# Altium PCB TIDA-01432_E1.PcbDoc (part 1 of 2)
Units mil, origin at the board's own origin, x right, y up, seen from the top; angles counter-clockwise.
Board outline 1228.35 x 2074.8 mil, 4 copper layers (Top Layer, Signal Layer 1, Signal Layer 2, Bottom Layer), stack 61.6 mil thick; 90 components, 49 nets, 292 pads, 293 vias.
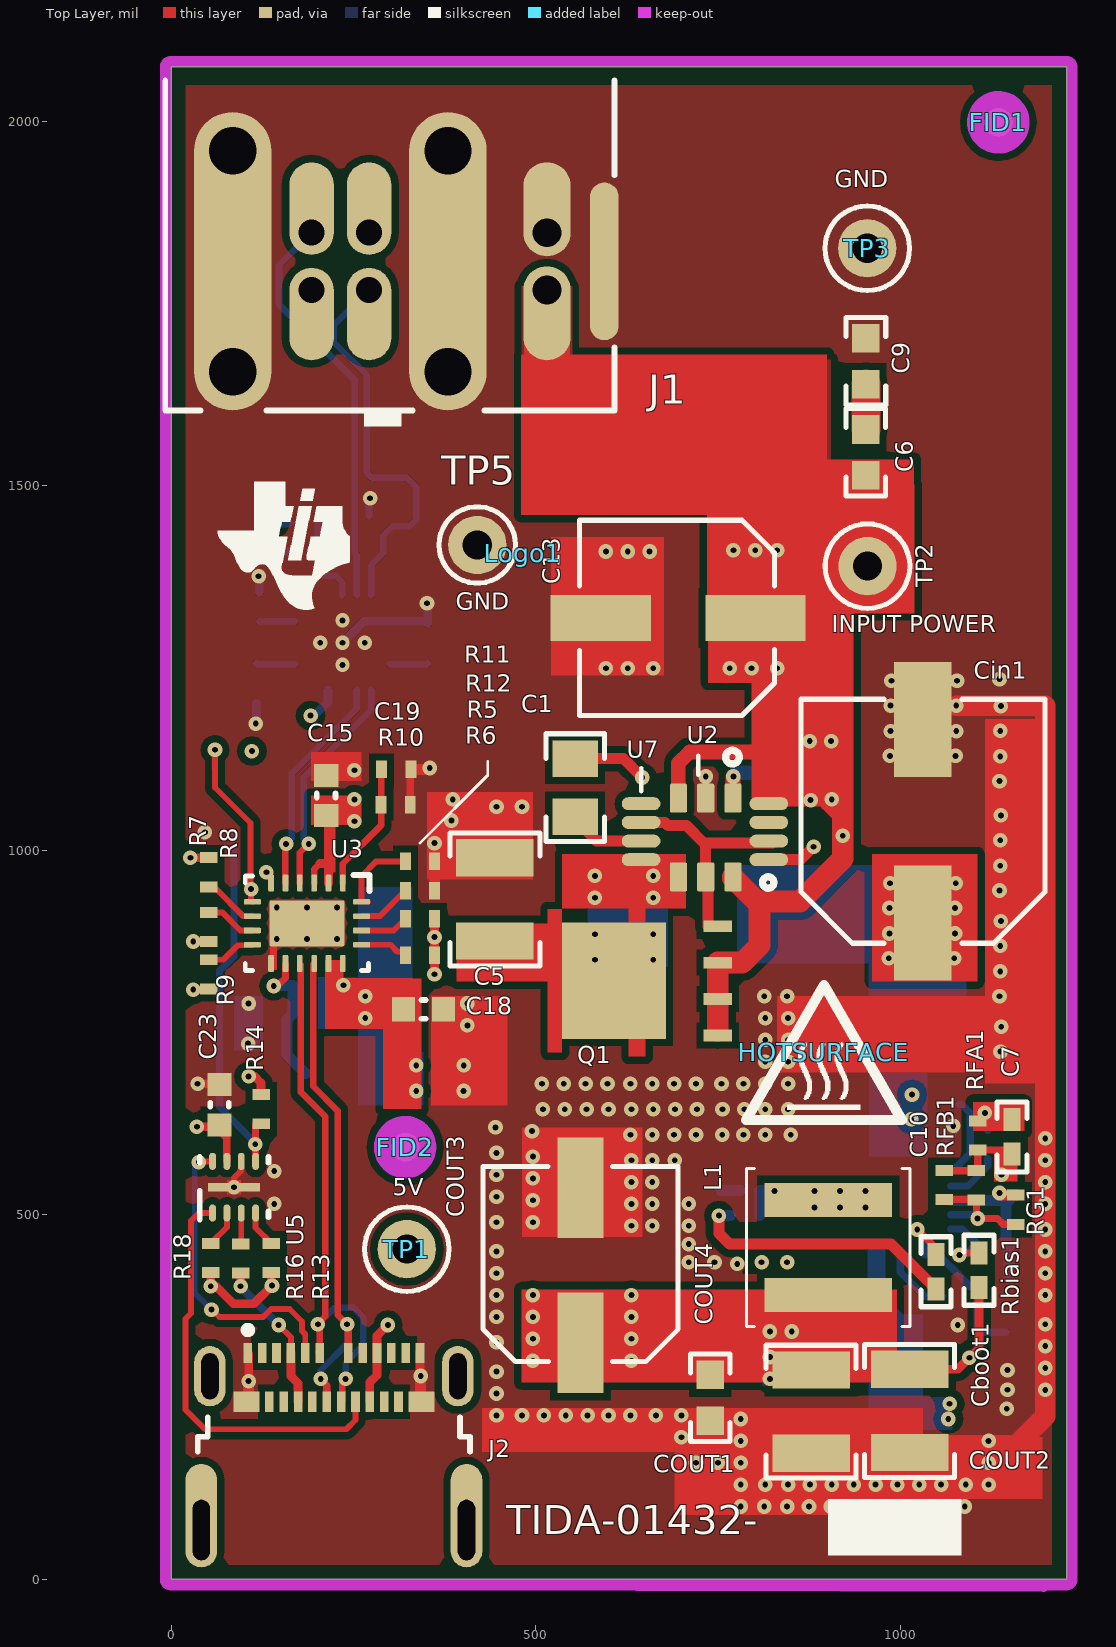
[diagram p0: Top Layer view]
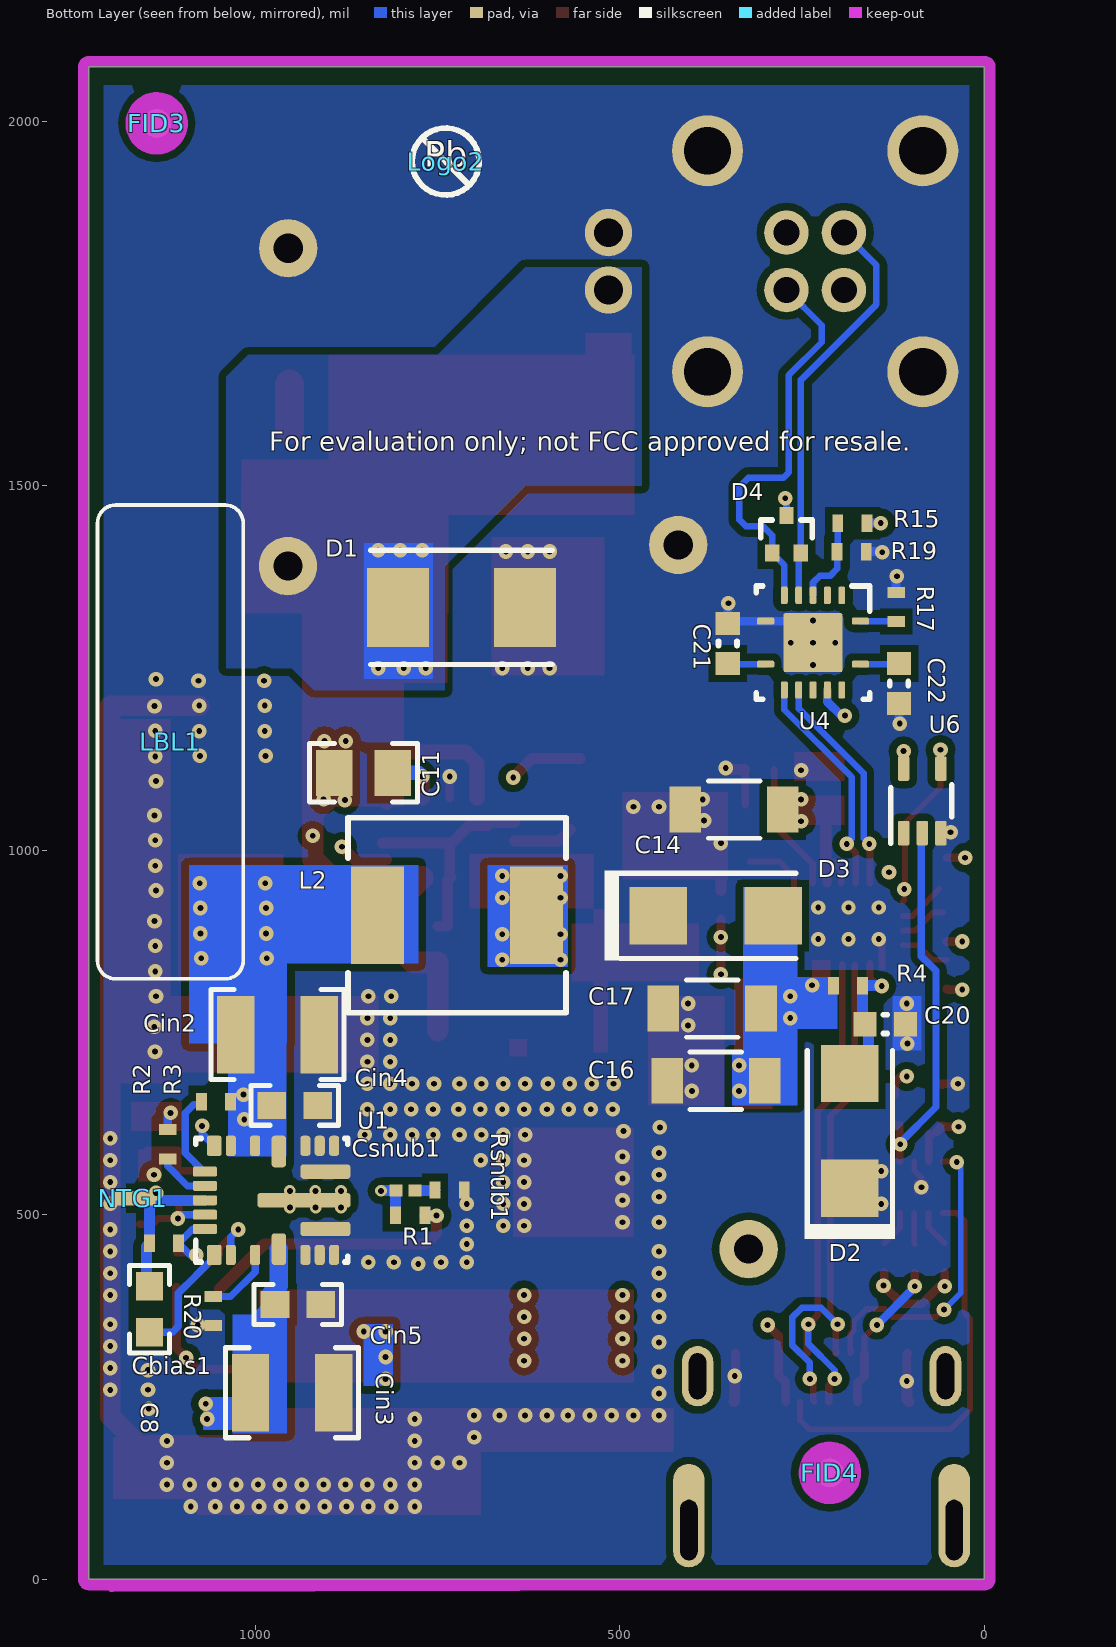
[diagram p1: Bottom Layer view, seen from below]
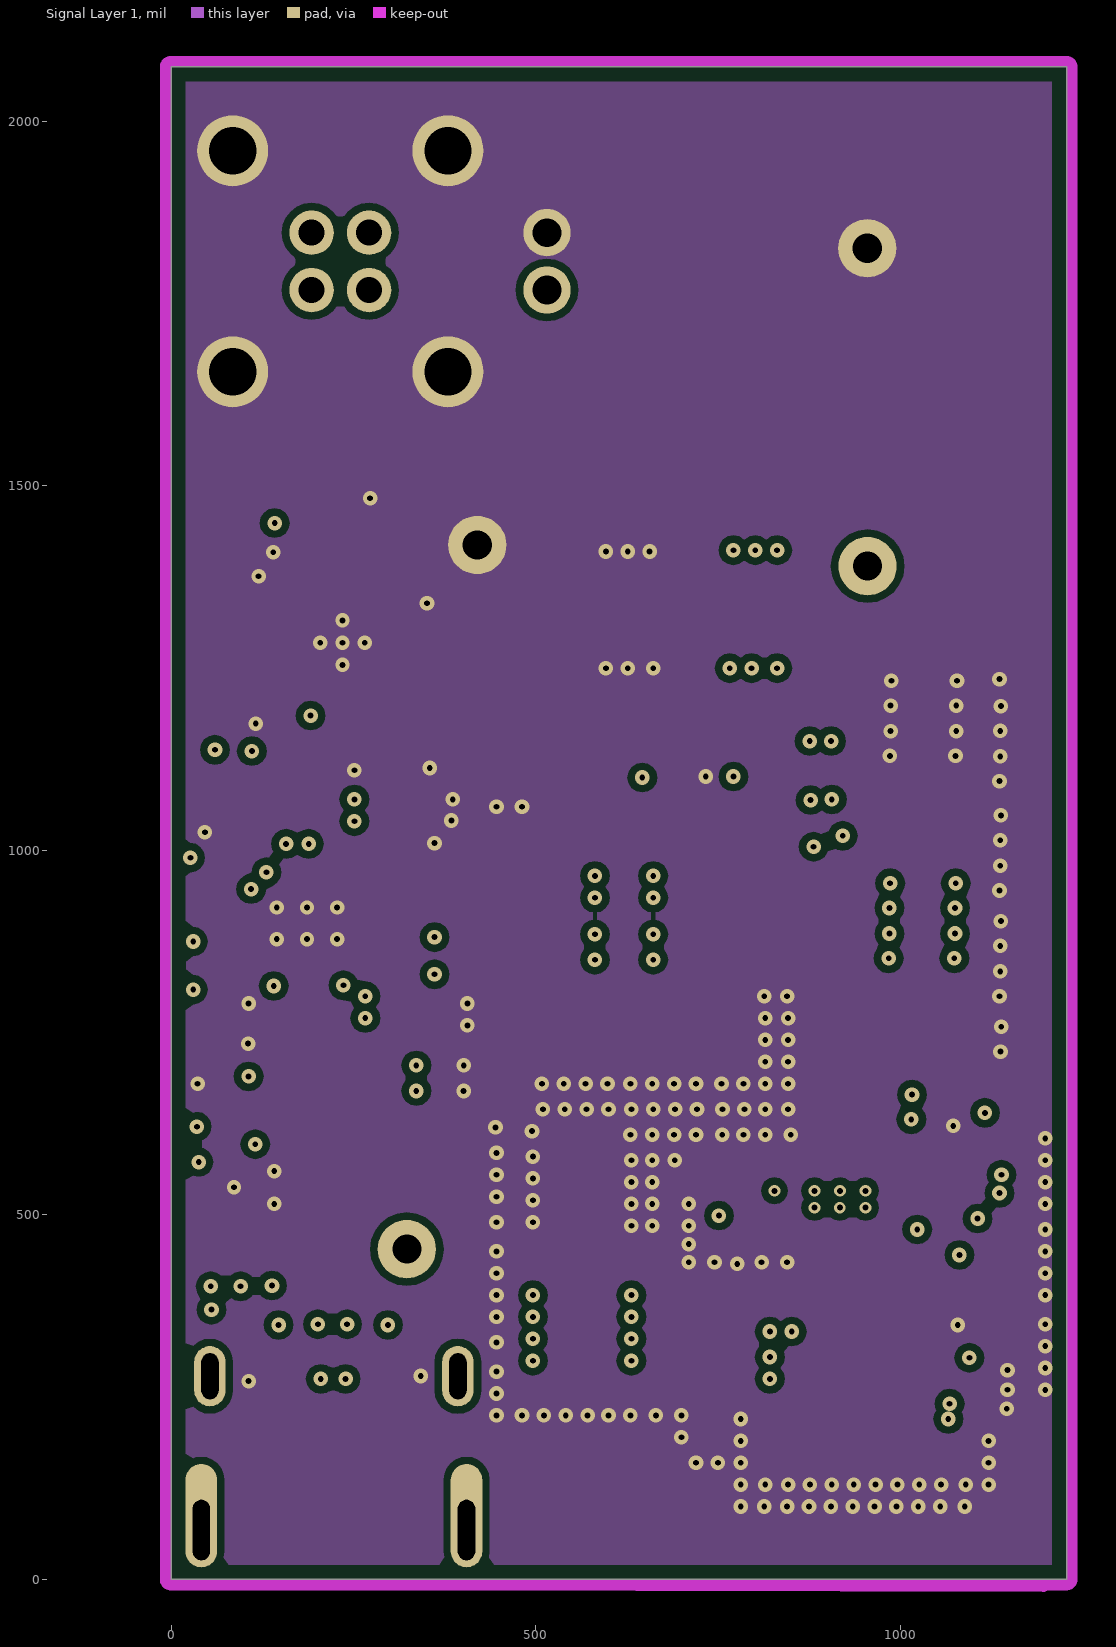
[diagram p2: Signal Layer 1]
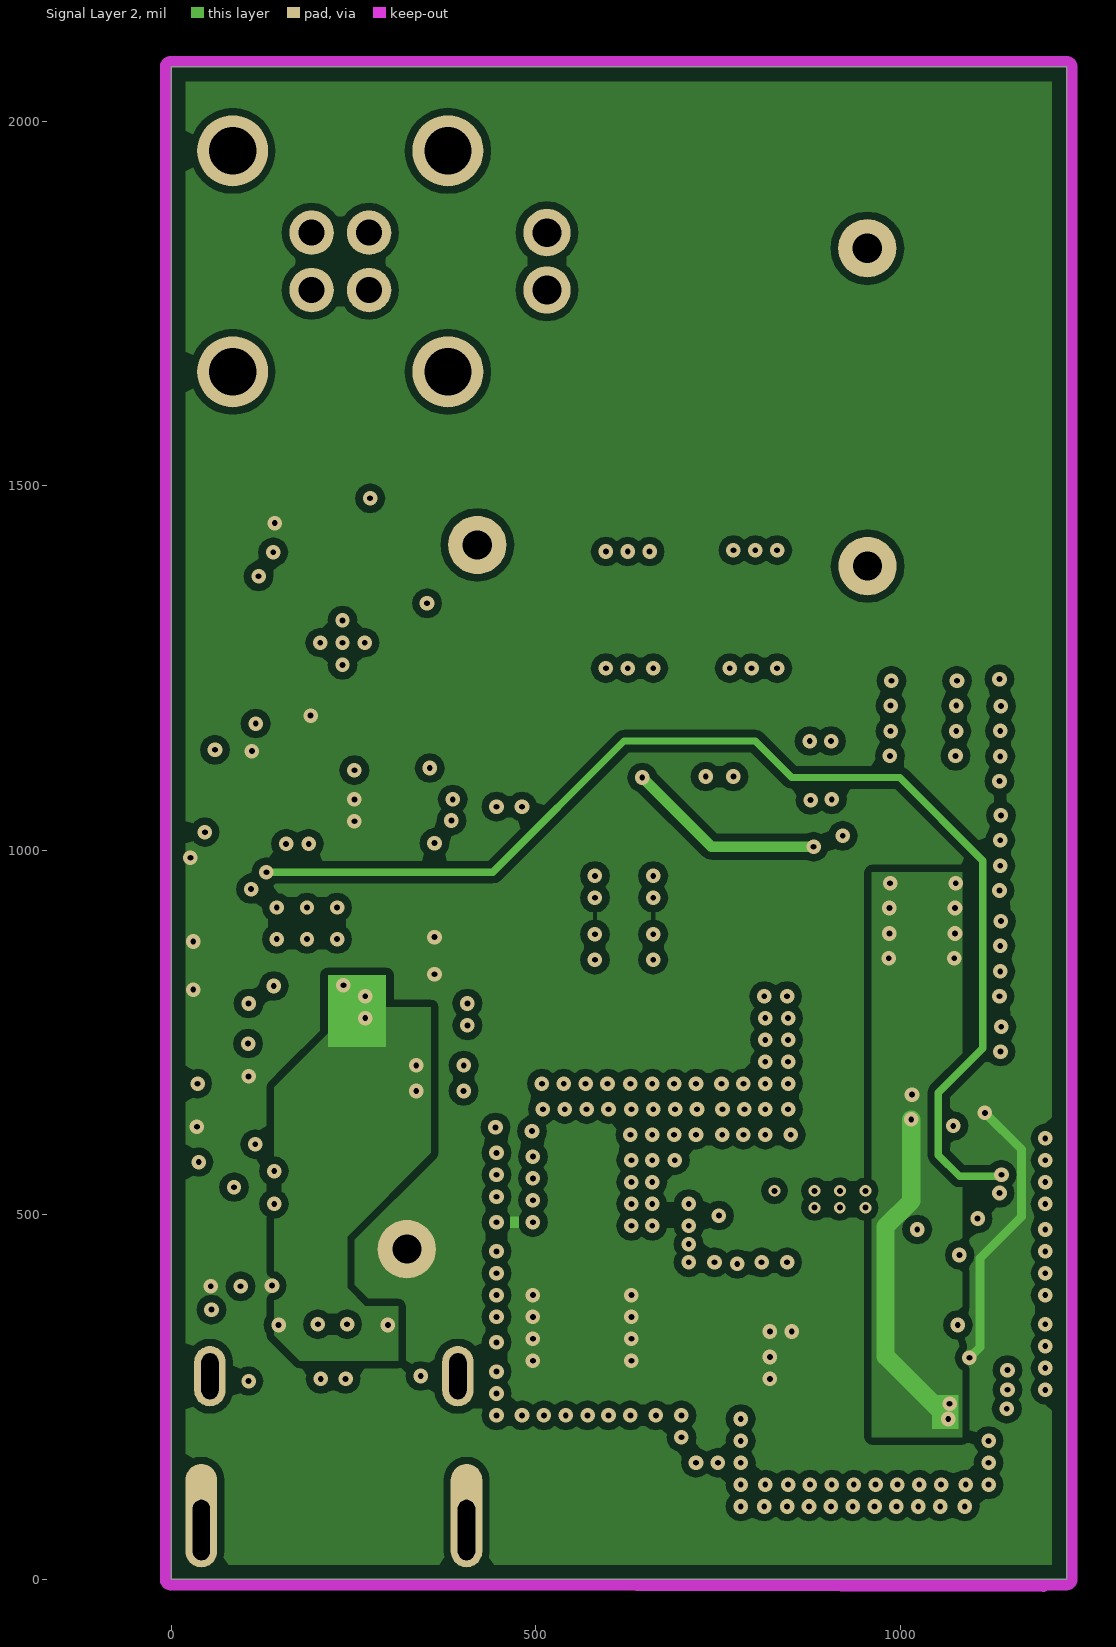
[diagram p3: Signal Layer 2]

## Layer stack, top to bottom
Top Solder: solder mask 0.4, Solder Resist, Dk 3.5
Top Layer: signal copper 1.4
Dielectric1: core 6, FR-4, Dk 4.8
Signal Layer 1: signal copper 1.4
Dielectric2: prepreg 44, Dk 4.2
Signal Layer 2: signal copper 1.4
Dielectric 3: core 6, Dk 4.2
Bottom Layer: signal copper 1.4
Bottom Solder: solder mask 0.4, Solder Resist, Dk 3.5

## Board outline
0,0 0,2074.8 1228.35,2074.8 1228.35,0

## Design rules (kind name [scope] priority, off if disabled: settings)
AcuteAngle [All] p1: minimum=4.50000000000000E+0001 checktracksonly=FALSE
AssemblyTestPointUsage [All] p1: valid=2
BoardOutlineClearance BoardOutlineClearance_MountingHoles [OnCopper and InComponentClass('Mounting Holes')] p1: gap=40
BoardOutlineClearance BoardOutlineClearance_Poly [OnCopper and IsPoly] p2: gap=20
BoardOutlineClearance [OnCopper and Not InComponentClass('Logo') and not InComponentClass('FiducialMark') and not InRegion(1000,500,4000,800) and not InPoly] p3: gap=15
Clearance Clearance_Keepouts [((IsTrack Or IsArc) And Not InPoly) And IsFree and IsKeepOut vs ((IsTrack Or IsArc) And Not InPoly) And IsFree and IsKeepOut] p1: gap=0
Clearance Clearance_Poly [InPolygon] p2: gap=10
Clearance [All] p3: gap=5
ComponentClearance ComponentClearance_U2_U7 [InComponent('U7') vs InComponent('U2')] p1: gap=0 collisioncheckmode=3 verticalgap=0 showdistances=FALSE
ComponentClearance ComponentClearance_MountingHoles_FiducialMarks [InComponentClass('Mounting Holes') vs InComponentClass('FiducialMark')] p2: gap=50 collisioncheckmode=3 verticalgap=10 showdistances=FALSE
ComponentClearance ComponentClearance_Shunt [InComponentClass('Header') vs InComponentClass('Shunt')] p3: gap=0 collisioncheckmode=3 verticalgap=0 showdistances=FALSE
ComponentClearance ComponentClearance_Logo [InComponentClass('Logo')] p4: gap=50 collisioncheckmode=3 verticalgap=10 showdistances=FALSE
ComponentClearance ComponentClearance_ScrewToNut [(HasFootprint('NY PMS 440 0025 PH')) vs (HasFootprint('Keystone_1902C'))] p5: gap=5 collisioncheckmode=3 verticalgap=10 showdistances=FALSE
ComponentClearance ComponentClearance_MountingHoles [InComponentClass('Mounting Holes')] p6: gap=250 collisioncheckmode=3 verticalgap=100000 showdistances=FALSE
ComponentClearance ComponentClearance_SmallPassives [HasFootprint('0201*') or HasFootprint('0402*') or HasFootprint('0508') or HasFootprint('0603*') or HasFootprint('0612') or HasFootprint('0805*') or HasFootprint('0815*') or HasFootprint('0830*') or HasFootprint('1206*') or HasFootprint('1210*') or HasFootprint('1808*') or HasFootprint('1812*') or HasFootprint('1825*') or HasFootprint('2010*') or HasFootprint('2220*') or HasFootprint('2225*') or HasFootprint('2512*') or HasFootprint('2728*') or HasFootprint('3518*') vs HasFootprint('0201*') or HasFootprint('0402*') or HasFootprint('0508') or HasFootprint('0603*') or HasFootprint('0612') or HasFootprint('0805*') or HasFootprint('0815*') or HasFootprint('0830*') or HasFootprint('1206*') or HasFootprint('1210*') or HasFootprint('1808*') or HasFootprint('1812*') or HasFootprint('1825*') or HasFootprint('2010*') or HasFootprint('2220*') or HasFootprint('2225*') or HasFootprint('2512*') or HasFootprint('2728*') or HasFootprint('3518*')] p7: gap=14.96 collisioncheckmode=3 verticalgap=10 showdistances=FALSE
ComponentClearance ComponentClearance_THtoSMT [IsThruComponent vs IsSMTComponent] p8: gap=40 collisioncheckmode=3 verticalgap=30 showdistances=FALSE
ComponentClearance ComponentClearance_THtoTH [IsThruComponent vs IsThruComponent] p9: gap=30 collisioncheckmode=3 verticalgap=30 showdistances=FALSE
ComponentClearance [All] p10: gap=20 collisioncheckmode=3 verticalgap=10 showdistances=FALSE
DiffPairsRouting [All] p1: maxlimit=100 minlimit=7.5 mostfreqgap=10 toplayer_prefgap=7.5 toplayer_minwidth=9 toplayer_maxwidth=15 toplayer_prefwidth=9 midlayer1_mingap=10 midlayer1_minwidth=15 midlayer1_maxwidth=15 midlayer1_prefwidth=15 midlayer2_mingap=10 midlayer2_minwidth=15 midlayer2_maxwidth=15 midlayer2_prefwidth=15 bottomlayer_prefgap=7.5 bottomlayer_minwidth=9 bottomlayer_maxwidth=15 bottomlayer_prefwidth=9 maxuncoupledlength=1000
FabricationTestPointUsage TestPointUsage [All] p1: valid=2 allowmultiple=FALSE
FabricationTestpoint Testpoint [All] p1: side=3 testpointundercomponent=TRUE minsize=40 maxsize=100 preferedsize=60 minholesize=0 maxholesize=40 preferedholesize=32 testpointgrid=1 allowsidetop=TRUE allowsidebottom=TRUE usegrid=TRUE gridtolerance=0.01
FanoutControl Fanout_LCC [IsLCC] p1: bgadir=Out bgaviamode=Centered fanoutstyle=Auto fanoutdirection=Alternating viagrid=1 // Fanout_LCC (Default Rule)
FanoutControl Fanout_BGA [IsBGA] p2: bgadir=Out bgaviamode=Centered fanoutstyle=Auto fanoutdirection=Alternating viagrid=1 // Fanout_BGA (Default Rule)
FanoutControl Fanout_Default [All] p4: bgadir=Out bgaviamode=Centered fanoutstyle=Auto fanoutdirection=Alternating viagrid=1 // Fanout_Default (Default Rule)
FanoutControl Fanout_Small [(CompPinCount < 5)] p5: bgadir=Out bgaviamode=Centered fanoutstyle=Auto fanoutdirection=OutThenIn viagrid=1 // Fanout_Small (Default Rule)
HoleSize [All] p1: absolutevalues=TRUE maxlimit=251 minlimit=7.87 maxpercent=80.000 minpercent=20.000
MinimumAnnularRing MinimumAnnularRing_ThermalPadVias [IsVia and InAnyComponent] p1: minimumring=5.91
MinimumAnnularRing [All] p2: minimumring=4
MinimumSolderMaskSliver MinimumSolderMaskSliver_Logo [InComponentClass('Logo') vs InComponentClass('Logo')] p1: minsoldermaskwidth=0.7
MinimumSolderMaskSliver [All] p2: minsoldermaskwidth=3.94
PlaneConnect [All] p1: planeconnectstyle=Relief reliefexpansion=10 reliefentries=4 reliefconductorwidth=10 reliefairgap=10
PolygonConnect [All] p1: connectstyle=Direct reliefconductorwidth=10 reliefentries=4 polygonreliefangle="90 Angle" airgapwidth=10
RoutingVias ThermalPadVias [IsVia and InAnyComponent] p1: holewidth=7.87 width=19.68 viastyle="Through Hole" minholewidth=7.87 minwidth=19.68 maxholewidth=12.99 maxwidth=23.62
RoutingVias [All] p2: holewidth=16 width=34 viastyle="Through Hole" minholewidth=7.87 minwidth=16 maxholewidth=40 maxwidth=65
ShortCircuit ShortCircuit_1 [InComponent('P1')  and ispad] p1: allowed=TRUE
ShortCircuit [All] p2: allowed=FALSE
SilkToBoardRegionClearance [Not ((IsComment or IsDesignator) And (Hide <> 'False')) and not InRegion(1000,500,4000,800)] p1:
SilkToSilkClearance SilkToSilkClearance_Pb-FreeLogo [(HasFootprint('Pb-Free_Overlay_Medium') OR HasFootprint('Pb-Free_Overlay_Small')) vs (HasFootprint('Pb-Free_Overlay_Medium') OR HasFootprint('Pb-Free_Overlay_Small'))] p1: silktosilkclearance=0
SilkToSilkClearance [All] p2: silktosilkclearance=4
SilkToSolderMaskClearance SilkToComponentPadClearance [(IsPad or IsFill or IsRegion) and InAnycomponent] p1: minsilkscreentomaskgap=4.9 clearancetoexposedcopper=TRUE
SilkToSolderMaskClearance "Silk to Solder Mask Opening" [All] p2: minsilkscreentomaskgap=4 clearancetoexposedcopper=FALSE
SolderMaskExpansion [All] p1: expansion=1.97
Width [All] p1: maxlimit=100 minlimit=6 preferedwidth=10 checkconnectedcopper=TRUE
14 further rules are at their usual default settings.

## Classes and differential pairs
component class "TIDA-01432 E1_Hardware": !PCB FID1 FID2 FID3 FID4 HOTSURFACE LBL1 Logo1 Logo2 Logo3 ZZ1 ZZ2 ZZ3 ZZ4
component class Logo: Logo1
component class Label: LBL1
component class FiducialMark: FID1 FID2 FID3 FID4
component class AssemblyNote: ZZ1 ZZ2 ZZ3 ZZ4
component class "TIDA-01432 E1 Schematic": C14 C15 C16 C17 C18 C19 C20 C21 C22 C23 D2 D3 D4 J1 J2 R4 R5 R6 R7 R8 R9 R10 R11 R12 R13 R14 R15 R16 R17 R18 R19 TP5 U3 U4 U5 U6
component class "TIDA-01432 E1 Power Schematic": C1 C2 C3 C5 C6 C7 C8 C9 C10 C11 C13 Cbias1 Cboot1 Cin1 Cin2 Cin3 Cin4 Cin5 COUT1 COUT2 COUT3 COUT4 Csnub1 D1 L1 L2 NTG1 Q1 R1 R2 R3 R20 Rbias1 RFA1 RFB1 RG1 Rsnub1 TP1 TP2 TP3 U1 U2 U7

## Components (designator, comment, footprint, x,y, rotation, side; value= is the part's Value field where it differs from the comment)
C1 "C2012X5R1H225K125AB" 0805_HV 554.35,1086 r90 top
C5 "GRM32ER71H106KA12L" 1210 444.27,932.82 r90 top
C6 "C0603C472J1GAC7867" 0603 953,1546 r90 top
C7 "GRM155R61A103KA01D" 0402 1153.35,607 r270 top
C8 "C1608X5R1V475K080AC" 0603 1145.16,370.69 r90 bottom
C9 "C0603C472J1GAC7867" 0603 953,1671 r270 top
C10 "C0402C120J3GACAUTO" 0402S 1060.42,541 r270 top
C11 "C2012X5R1H225K125AB" 0805_HV 851.82,1106.48 r180 bottom
C13 "APXE100ARA121MF61G" CAPSMT_62_F61 696.35,1320 r180 top
C14 "GCM31CR71A106KA64L" 1206_190 343.35,1056 r0 bottom
C15 "GCM188R71H104KA57D" 0603L 212.59,1075.26 r90 top
C16 "GCM31CR71A106KA64L" 1206_190 368.35,684 r0 bottom
C17 "GCM31CR71A106KA64L" 1206_190 373.35,783 r0 bottom
C18 "GCM188R71H104KA57D" 0603L 346.35,782 r0 top
C19 "C1005X5R1E225K050BC" 0402S 308.77,1111 r0 top
C20 "GCM188R71H104KA57D" 0603L 135.99,761.7 r180 bottom
C21 "GCM188R71H104KA57D" 0603L 352.03,1284 r90 bottom
C22 "GCM188R71H104KA57D" 0603L 117.03,1229 r270 bottom
C23 "GCM188R71H104KA57D" 0603L 66.35,651 r90 top
Cbias1 "C1005X7R1H104K050BB" 0402S 1125.35,461 r180 bottom
Cboot1 "C1005X5R1A474K050BB" 0402 1049.15,422 r90 top
Cin1 "EEE-FK1J470P" SM_RADIAL_F 1031.35,1040 r90 top
Cin2 "GRM32ER71H106KA12L" 1210 969.65,747.2 r180 bottom
Cin3 "GRM32ER71H106KA12L" 1210 949.65,256 r180 bottom
Cin4 "GCM188R71E473KA37D" 0603 946.11,650.21 r180 bottom
Cin5 "GCM188R71E473KA37D" 0603 941.65,377 r180 bottom
COUT1 "GRM32ER61E226KE15L" 1210_270 877.81,230 r90 top
COUT2 "GRM32ER61E226KE15L" 1210_270 1013,231 r90 top
COUT3 "APXE100ARA121MF61G" CAPSMT_62_F61 562.65,430 r90 top
COUT4 "GCM188R71E473KA37D" 0603 739.65,249 r270 top
Csnub1 "GRM033R61A332KA01D" 0201 794,533.65 r0 bottom
D1 "SMBJ28CA-13-F" SMB-Bi 717.35,1333.32 r180 bottom
D2 "SMAJ16CA" SMA 184.48,615.26 r90 bottom
D3 "SMAJ16CA" SMA 368.4,910.2 r180 bottom
D4 "ESDR0502BT1G" SOT-416 271.35,1433.68 r90 bottom
FID1 "Fiducial" Fiducial10-20 1134.83,1998.77 r0 top
FID2 "Fiducial" Fiducial10-20 321,593 r0 top
FID3 "Fiducial" Fiducial10-20 1135.33,1997.27 r180 bottom
FID4 "Fiducial" Fiducial10-20 212,146 r180 bottom
HOTSURFACE "CAUTION HOT SURFACE" IEC_HotSurface_Small 895.5,723 r0 top
J1 "99S20D-40MA5-D" Rosenberger_99S20D-40MA5-D 300,2066 r0 top
J2 "201267-0001" Molex_201267-0001 223.35,-2 r0 top
L1 "XAL5050-103MEB" XAL5050 901.46,455.22 r270 top
L2 "SRP6540-8R2M" SRP6540 723.35,911 r0 bottom
LBL1 "Size: 0.65\" x 0.20 \"" Label_650x200 1116.58,1148.77 r90 bottom
Logo1 "Texas Instruments" TI_Stacked_Overlay_Small 482.5,1407.75 r0 top
Logo2 "Pb-Free Symbol" Pb-Free_Overlay_Small 739,1945 r180 bottom
Logo3 "FCC disclaimer" FCC_disclaimer 2119,1540 r180 bottom
NTG1 "Net-Tie" Net-Tie_50milWide_30milLong 1167.35,523 r0 bottom net-tie
Q1 "SQJ422EP-T1-GE3" PowerPAK_SO-8L 639.35,821 r180 top
R1 "CRCW04020000Z0ED" 0402S 787.5,499.35 r180 bottom
R2 "CRCW0805100KFKEA" 0402S 1120.35,596.96 r270 bottom
R3 "MCR01MZPJ000" 0402S 1054,655 r180 bottom
R4 "CRCW04025K11FKED" 0402S 186.95,814.61 r0 bottom
R5 "RMCF0402FT100K" 0402S 341.35,906 r180 top
R6 "RMCF0402FT100K" 0402S 341.35,856 r180 top
R7 "RMCF0402FT100K" 0402S 51.35,970 r270 top
R8 "RMCF0402FT100K" 0402S 51.35,895 r90 top
R9 "RMCF0402FT100K" 0402S 51.35,830 r90 top
R10 "CRCW04022K00FKED" 0402S 308.03,1062.82 r180 top
R11 "CRCW040215K4FKED" 0402S 341.35,985 r180 top
R12 "CRCW040280K6FKED" 0402S 341.35,945 r180 top
R13 "CRCW0402200KFKED" 0402S 137.35,441 r270 top
R14 "CRCW0402200KFKED" 0402S 123.35,645 r90 top
R15 "CRCW040226K1FKED" 0402S 181.08,1449.04 r180 bottom
R16 "CRCW0402200KFKED" 0402S 95.35,440 r90 top
R17 "CRCW04021K00FKED" 0402S 121.03,1334 r270 bottom
R18 "CRCW040210K0FKED" 0402S 54.35,441 r270 top
R19 "CRCW040249K9FKED" 0402S 182.03,1410 r0 bottom
R20 "MCR01MZPJ000" 0402S 1058,368 r270 bottom
Rbias1 "CRCW04023R00JNED" 0402 1108.35,424 r270 top
RFA1 "CRCW04022K94FKED" 0402S 1106.35,609 r90 top
RFB1 "ERJ-2RKF4992X" 0402S 1104.81,540.68 r270 top
RG1 "CRCW040212K1FKED" 0402S 1158.75,507.11 r270 top
Rsnub1 "CRCW04028R20JNED" 0402S 733.5,534.15 r0 bottom
TP1 "5000" Keystone5000 323.35,453 r90 top
TP2 "5000" Keystone5000 955.35,1390 r90 top
TP3 "5001" Keystone5001 955,1826 r90 top
TP5 "5001" Keystone5001 420,1419 r90 top
U1 "LMS3635AQRNLRQ1" RNL0022A_NV 977.65,520 r90 bottom
U2 "LM74700QDDCRQ1" DDC0006A_N 733.35,1017.68 r270 top
U3 "TPS254900IRVCRQ1" RVC0020A 186.35,900 r270 top
U4 "TUSB213RGYR" RGY0014A 235.03,1285 r270 bottom
U5 "TUSB319DRFRQ1" DRF0008A 86.35,538 r90 top
U6 "SN74AHCT1G04DCKR" DCK0005A_N 85.15,1068 r90 bottom
U7 "LM74610QDGKRQ1" DGK0008A_N 732.35,1025.69 r180 top
ZZ1 "This Assembly Note is for PCB labels only" AssemblyNoteLabel 443,5143 r0 top
ZZ2 "These assemblies are ESD sensitive, ESD precautions shall be observed." AssemblyNote 456,4971 r0 top
ZZ3 "These assemblies must be clean and free from flux and all contaminants. Use of no clean flux is not acceptable." AssemblyNote 456,4830 r0 top
ZZ4 "These assemblies must comply with workmanship standards IPC-A-610 Class 2, unless otherwise specified." AssemblyNote 451,4683 r0 top

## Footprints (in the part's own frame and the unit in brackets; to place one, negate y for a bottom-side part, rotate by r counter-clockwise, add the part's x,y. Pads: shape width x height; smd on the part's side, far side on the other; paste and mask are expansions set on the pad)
0201 [mm] "Data from Kemet datasheet CC101_COM dated 7/28/11"
  rect 0.46x0.42 smd mask+0.048: 1(-0.33,0) 2(0.33,0)
  body extent -0.31,-0.16 0.31,0.16, height 0.26
0402 [mm] "0402 from SM-752 data"
  rect 0.8x0.6 smd: 1(-0.6,0) 2(0.6,0)
  silkscreen extent -1.22,-0.52 1.22,0.52, body extent -0.55,-0.3 0.55,0.3, height 0.6
0402S [mil] "Based on C0402S footprint from PADS legacy"
  rect 15x24 smd: 1(-20,0) 2(20,0)
  body extent -22,-12 22,12, height 24
0603 [mm] "0603 from SM-752 data"
  rect 1x0.95 smd: 1(-0.8,0) 2(0.8,0)
  silkscreen extent -1.52,-0.69 1.52,0.69, body extent -0.87,-0.47 0.87,0.47, height 1
0603L [mm] "0603 from SM-752 data"
  rect 0.8x0.85 smd: 1(-0.7,0) 2(0.7,0)
  silkscreen extent -0.07,-0.33 0.07,0.33, body extent -0.87,-0.47 0.87,0.47, height 1
0805_HV [mil] "0805 with 30mil clearance between pads"
  rect 50x63 smd: 1(-40,0) 2(40,0)
  silkscreen extent -74,-40 74,40, body extent -43,-29 43,29, height 57
1206_190 [mm] "1206_190"
  rect 1.1x1.6 smd: 1(-1.7,0) 2(1.7,0)
  silkscreen extent -0.9,-1 0.9,1, body extent -1.75,-0.95 1.75,0.95, height 1.9
1210 [mm] "1210 from SM-752 data"
  rect 1.3x2.7 smd: 1(-1.45,0) 2(1.45,0)
  silkscreen extent -2.32,-1.57 2.32,1.57, body extent -1.7,-1.35 1.7,1.35, height 1.35
1210_270 [mm] "1210"
  rect 1.3x2.7 smd: 1(-1.45,0) 2(1.45,0)
  silkscreen extent -2.32,-1.57 2.32,1.57, body extent -1.7,-1.35 1.7,1.35, height 2.7
AssemblyNote [mil] "Assembly Note"
AssemblyNoteLabel [mil] "Assembly Note for PCB Labels"
CAPSMT_62_F61 [mm] "6.3 x 5.8mm:  Chemi-Con F61"
  rect 3.5x1.6 smd: 1(-2.675,0.025) 2(2.725,0.025)
  silkscreen extent -3.34,-3.38 3.46,3.42, body extent -3.37,-3.38 3.46,3.43, height 6.1
DCK0005A_N [mm] "SOT353, 5-Leads, Body 2x1.3mm, Pitch 0.65mm, Lead Span 2.1mm, IPC Medium Density"
  rrect25% 0.85x0.4 smd: 1(-1.125,0.65) 2(-1.125,0) 3(-1.125,-0.65) 4(1.125,-0.65) 5(1.125,0.65)
  silkscreen extent -1.48,-1.02 0.55,1.1, body extent -1.14,-1 1.14,1, height 0.95
DDC0006A_N [mm]
  rrect17% 1x0.6 smd: 1(-1.375,0.95) 2(-1.375,0) 3(-1.375,-0.95) 4(1.375,-0.95) 5(1.375,0) 6(1.375,0.95)
  body extent -1.43,-1.48 1.43,1.49, height 0.92
DGK0008A_N [mm] "TSOP, 8-Leads, Body 3x3mm, Pitch 0.65mm, IPC Medium Density"
  oval 1.35x0.45 smd: 1(-2.225,0.975) 2(-2.225,0.325) 3(-2.225,-0.325) 4(-2.225,-0.975) 5(2.225,-0.975) 6(2.225,-0.325) 7(2.225,0.325) 8(2.225,0.975)
  body extent -2.45,-1.5 2.45,1.5, height 0.96
DRF0008A [mm] "SON, 8-Leads, Body 2x2mm, Pitch 0.5mm, Thermal Pad 1.8x0.3/0.5mm, TI Recommended"
  oval 0.6x0.24 smd: 1(-0.9,0.75) 2(-0.9,0.25) 3(-0.9,-0.25) 4(-0.9,-0.75) 5(0.9,-0.75) 6(0.9,-0.25) 7(0.9,0.25) 8(0.9,0.75)
  rect 0.3x1.8 smd paste-0.15: 9(0,0)
  Top Layer region: -0.25,-0.25 0.25,-0.25 0.25,0.25 -0.25,0.25
  silkscreen extent -1.12,-1.2 1.05,1.2, body extent -1.05,-1.05 1.05,1.05, height 0.81
FCC_disclaimer [mil]
Fiducial10-20 [mm]
  round 1 smd mask+0.5: 1(0,0)
  Top Layer keep-out circle w1.178: c0,0 r0.5
IEC_HotSurface_Small [mil]
  silkscreen extent -107,-93 107,92
Keystone5000 [mil] "For Keystone 500x miniature loop terminals"
  round 80 hole 40: 1(0,0)
  silkscreen extent -58,-58 58,58, body extent -49,-49 49,49, height 182
Keystone5001 [mil] "For Keystone 500x miniature loop terminals"
  round 80 hole 40: 1(0,0)
  silkscreen extent -58,-58 58,58, body extent -49,-49 49,49, height 182
Label_650x200 [mil] "Thermal Transfer Label"
  round 1 on Mech14: 0(0,0)
  silkscreen extent -325,-100 325,100, body extent -325,-100 325,100, height 1
Molex_201267-0001 [mm] "Receptacle, USB TYPE C, R/A, SMT"
  rect 0.3x0.7 smd: A1(-3,7.94) A2(-2.5,7.94) A3(-2,7.94) A4(-1.5,7.94) A5(-1,7.94) A6(-0.5,7.94) A7(0.5,7.94) A8(1,7.94) A9(1.5,7.94) A10(2,7.94) A11(2.5,7.94) A12(3,7.94) B2(2.25,6.24) B3(1.75,6.24) B4(1.25,6.24) B5(0.75,6.24) B6(0.25,6.24) B7(-0.25,6.24) B8(-0.75,6.24) B9(-1.25,6.24) B10(-1.75,6.24) B11(-2.25,6.24)
  rect 0.9x0.7 smd: B1(3.05,6.24) B12(-3.05,6.24)
  oval 1.1x2.1 hole 0.6 slot 1.6 at 90 deg: S1(-4.32,7.13) S2(4.32,7.13)
  oval 1.1x3.6 hole 0.6 slot 2.1 at 90 deg copper offset 0,0.5: S3(-4.62,1.77) S4(4.62,1.77)
  silkscreen extent -4.74,4.5 4.74,8.86, body extent -4.74,-0.15 4.75,8.15, height 3.86
Net-Tie_50milWide_30milLong [mil] "50mil net tie, no solder mask opening, no solder paste"
  rect 30x20 smd paste-20 mask-20: 1(-15,0) 2(15,0)
Pb-Free_Overlay_Small [mil]
  silkscreen extent -46,-46 46,46
PowerPAK_SO-8L [mm] "based on Vishay recommended land pattern Document 63818 Feb 7, 2012"
  rect 1x0.41 smd: 1(-2.805,1.905) 2(-2.805,0.635) 3(-2.805,-0.635) 4(-2.805,-1.905)
  rect 3.63x4.061 smd: 5(0.805,0)
  Top Layer region: 2.615,-2.5 3.125,-2.5 3.125,2.5 2.615,2.5
  Top Layer region: -0.298,2.03 0.298,2.03 0.298,2.64 -0.298,2.64
  Top Layer region: -0.298,-2.64 0.298,-2.64 0.298,-2.03 -0.298,-2.03
  body extent -3.07,-2.57 3.08,2.57, height 1.21
RGY0014A [mm] "QFN, 14-Leads, Body 3.5x3.5mm, Pitch 0.5mm, Thermal Pad 2.05x2.05mm, TI Recommended"
  rrect42% 0.24x0.6 smd: 1(-0.75,1.65) 7(-0.75,-1.65) 8(0.75,-1.65) 14(0.75,1.65)
  rrect42% 0.6x0.24 smd: 2(-1.65,1) 3(-1.65,0.5) 4(-1.65,0) 5(-1.65,-0.5) 6(-1.65,-1) 9(1.65,-1) 10(1.65,-0.5) 11(1.65,0) 12(1.65,0.5) 13(1.65,1)
  rrect11% 0.92x0.92 on Bottom Paste: 15(-0.56,-0.56) 15(-0.56,0.56) 15(0.56,-0.56) 15(0.56,0.56)
  rrect5% 2.05x2.05 smd paste-1.025: 15(0,0)
  silkscreen extent -1.98,-1.97 1.98,1.97, body extent -1.75,-1.75 1.75,1.75, height 0.97
RNL0022A_NV [mm] "VQFN, 22 pin, 0.5 mm pitch"
  rrect25% 0.7x0.5 smd paste-0.05 mask-0.05: 1(-1.9,2) 17(1.9,2)
  rrect40% 0.7x0.35 smd paste-0.05 mask-0.05: 2(-1.9,1.425) 3(-1.9,0.575) 15(1.9,0.575) 16(1.9,1.425)
  rrect40% 1.1x0.5 smd paste-0.25 mask-0.05: 4(-1.7,-0.25) 14(1.7,-0.25)
  rrect25% 0.4x0.4 on Bottom Paste: 4A(-2,-0.25) 4B(-1.4,-0.25) 14A(1.4,-0.25) 14B(2,-0.25)
  rrect57% 0.7x0.35 smd paste-0.05 mask-0.05: 5(-1.9,-1.175) 6(-1.9,-1.675) 7(-1.9,-2.175) 11(1.9,-2.175) 12(1.9,-1.675) 13(1.9,-1.175)
  rrect40% 0.5x1.74 smd paste-0.25 mask-0.05: 8(-1,-1.875) 10(1,-1.875)
  rrect25% 0.4x0.66 on Bottom Paste: 8A(-1,-1.445) 8B(-1,-2.305) 10A(1,-1.445) 10B(1,-2.305)
  rrect40% 0.5x3.25 smd paste-0.25 mask-0.05: 9(0,-1.125)
  rrect25% 0.4x0.63 on Bottom Paste: 9A(0,0.12) 9B(0,-0.71) 9C(0,-1.54) 9D(0,-2.37)
  rrect40% 0.35x0.85 smd paste-0.05 mask-0.05: 18(1,2.325) 19(0.5,2.325) 20(0,2.325) 21(-0.5,2.325) 22(-1,2.325)
  silkscreen extent -2.15,-2.65 2.15,2.65, body extent -2,-2.5 2,2.5, height 0.9
Rosenberger_99S20D-40MA5-D [mm] "Right Angle Plug for PCB, 6-Lead, TH"
  round 1.55 hole 0.9: 1(-0.725,-7.55) 2(-0.725,-5.55) 3(-2.725,-5.55) 4(-2.725,-7.55)
  round 1.65 hole 1: 5(5.475,-7.55) 6(5.475,-5.55)
  oval 2.7x10.4 smd: S1(-5.475,-6.55) S2(2.025,-6.55)
  oval 1x5.5 smd: S3(7.475,-6.55)
  round 2.475 hole 1.65: ""(-5.475,-10.4) ""(-5.475,-2.7) ""(2.025,-10.4) ""(2.025,-2.7)
  oval 1.55x3.225 smd: ""(-2.725,-8.387) ""(-2.725,-4.713) ""(-0.725,-8.387) ""(-0.725,-4.713)
  oval 1.65x3.275 smd: ""(5.475,-8.362) ""(5.475,-4.738)
  silkscreen extent -7.82,-12.3 7.83,-0.25, body extent -7.82,-11.75 7.83,15.7, height 14.15
RVC0020A [mm] "TI"
  rrect50% 0.6x0.2 smd: 1(-1.4,1.25) 2(-1.4,0.75) 3(-1.4,0.25) 4(-1.4,-0.25) 5(-1.4,-0.75) 6(-1.4,-1.25) 11(1.4,-1.25) 12(1.4,-0.75) 13(1.4,-0.25) 14(1.4,0.25) 15(1.4,0.75) 16(1.4,1.25)
  rrect50% 0.2x0.6 smd: 7(-0.75,-1.9) 8(-0.25,-1.9) 9(0.25,-1.9) 10(0.75,-1.9) 17(0.75,1.9) 18(0.25,1.9) 19(-0.25,1.9) 20(-0.75,1.9)
  rrect9% 1.47x1.15 on Top Paste: 21(0,0.675) 21(0,-0.675)
  rrect6% 1.6x2.6 smd paste-1: 21(0,0)
  silkscreen extent -1.68,-2.15 1.65,2.18, body extent -1.55,-2.05 1.55,2.05, height 0.8
SM_RADIAL_F [mm] "8 x 10.2mm:  Panasonic F"
  rect 4x2 smd: 1(-3.55,0) 2(3.55,0)
  silkscreen extent -4.25,-4.25 4.25,4.25, body extent -4.25,-4.25 4.25,4.25, height 10.5
SMA [mm] "Molded Diode, 2-Leads, Body 4.3x2.6mm, IPC Medium Density, based on OnSemi component dimensions and land pattern"
  rect 2x2 smd: 1(-2,0) 2(2,0)
  silkscreen extent -3.76,-1.57 2.79,1.57, body extent -2.6,-1.3 2.6,1.3, height 2.42
SMB-Bi [mil] "Molded Diode, 2-Leads, Body 5.4x3.6mm, IPC Medium Density, based on OnSemi component dimensions"
  rect 85x107.99 smd: 1(-87.01,0) 2(87.01,0)
  silkscreen extent -125,-79 125,79, body extent -104,-73 104,73, height 89
SOT-416 [mm] "NXP recommended footprint."
  rect 0.6x0.5 smd: 1(-0.65,0.5) 2(-0.65,-0.5) 3(0.65,0)
  silkscreen extent -0.13,-0.9 0.5,0.9, body extent -0.8,-0.9 0.8,0.9, height 0.82
SRP6540 [mm] "Bourns"
  rect 1.85x3.4 smd: 1(-2.775,0) 2(2.775,0)
  silkscreen extent -3.8,-3.4 3.8,3.4, body extent -3.75,-3.35 3.75,3.35, height 4
TI_Stacked_Overlay_Small [mil]
  silkscreen extent -418,-78 -237,98
XAL5050 [mm] "CoilCraft XAL5050 5.28 x 5.48 x 5.1 mm"
  rect 1.18x4.44 smd: 1(-1.655,0) 2(1.655,0)
  silkscreen extent -2.75,-2.85 2.75,2.85, body extent -2.74,-2.84 2.74,2.84, height 5.1

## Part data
C1 C11: "CAP, CERM, 2.2 µF, 50 V, +/- 10%, X5R, 0805"
C5: "CAP, CERM, 10uF, 50V, +/-10%, X7R, 1210"
C6 C9: "CAP, CERM, 4700 pF, 100 V, +/- 5%, C0G/NP0, 0603"
C7: "CAP, CERM, 0.01 µF, 10 V, +/- 10%, X5R, 0402"
C8: "CAP, CERM, 4.7 µF, 35 V, +/- 10%, X5R, 0603"
C10: "CAP, CERM, 12 pF, 25 V, +/- 5%, C0G/NP0, AEC-Q200 Grade 1, 0402"
C13 COUT3: "CAP, AL, 120 µF, 10 V, +/- 20%, 0.025 ohm, SMD"
C14 C16 C17: "CAP, CERM, 10 µF, 10 V, +/- 10%, X7R, AEC-Q200 Grade 1, 1206_190"
C15 C18 C20 C21 C22 C23: "CAP, CERM, 0.1 µF, 50 V, +/- 10%, X7R, 0603"
C19: "CAP, CERM, 2.2 µF, 25 V, +/- 10%, X5R, 0402"
Cbias1: "CAP, CERM, 0.1 µF, 50 V, +/- 10%, X7R, 0402"
Cboot1: "CAP, CERM, 0.47 µF, 10 V, +/- 10%, X5R, 0402"
Cin1: "CAP, AL, 47 µF, 63 V, +/- 20%, 0.65 ohm, SMD"
Cin2 Cin3: "CAP, CERM, 10 µF, 50 V, +/- 10%, X7R, 1210"
Cin4 Cin5 COUT4: "CAP, CERM, 0.047 µF, 25 V, +/- 10%, X7R, AEC-Q200 Grade 1, 0603"
COUT1 COUT2: "CAP, CERM, 22 µF, 25 V, +/- 10%, X5R, 1210"
Csnub1: "CAP, CERM, 3300 pF, 10 V, +/- 10%, X5R, 0201"
D1: "Diode, TVS, Bi, 28 V, 45.4 Vc, SMB"
D2 D3: "Diode, TVS, Bi, 16 V, 400 W, SMA"
D4: "Diode, TVS, Uni, 5 V, 20 W, AEC-Q101, SOT-416"
FID1 FID2 FID3 FID4: "Fiducial mark.  There is nothing to buy or mount."
HOTSURFACE: library part IEC_HotSurface, "IEC 61010-1 Hot Surface Warning"
J1: "RF Coaxial Connector, Bordeaux, R/A, TH"
J2: "Receptacle, USB TYPE C, R/A, SMT"
L1: "Inductor, Shielded, Composite, 10 µH, 4.9 A, 0.05 ohm, SMD"
L2: "Inductor, Shielded, Ferrite, 8.2 µH, 4.5 A, 0.0505 ohm, SMD"
LBL1: library part THT-14-423-10, "Thermal Transfer Printable Labels, 0.650\" W x 0.200\" H - 10,000 per roll"
Logo1: library part TI_Logo, "Texas Instrument Corporate Signature"
Logo2: library part Pb-Free
Logo3: library part FCC_disclaimer, "FCC_disclaimer"
NTG1: "Single point connection between nets."
Q1: "MOSFET, N-CH, 40 V, 75 A, PowerPAK_SO-8L"
R1 R3 R20: "RES, 0, 5%, 0.063 W, 0402"
R2: library part ERJ-2RKF1001X, "RES, 1.00 k, 1%, 0.1 W, 0402"
R4: "RES, 5.11 k, 1%, 0.063 W, 0402"
R5 R6 R7 R8 R9: "RES, 100 k, 1%, 0.063 W, AEC-Q200 Grade 0, 0402"
R10: "RES, 2.00 k, 1%, 0.063 W, 0402"
R11: "RES, 15.4 k, 1%, 0.063 W, 0402"
R12: "RES, 80.6 k, 1%, 0.063 W, 0402"
R13 R14 R16: "RES, 200 k, 1%, 0.063 W, 0402"
R15: "RES, 26.1 k, 1%, 0.063 W, 0402"
R17: "RES, 1.00 k, 1%, 0.063 W, 0402"
R18: "RES, 10.0 k, 1%, 0.063 W, 0402"
R19: "RES, 49.9 k, 1%, 0.063 W, 0402"
Rbias1: "RES, 3.0, 5%, 0.063 W, 0402"
RFA1: "RES, 2.94 k, 1%, 0.063 W, 0402"
RFB1: "RES, 49.9 k, 1%, 0.1 W, AEC-Q200 Grade 0, 0402"
RG1: "RES, 12.1 k, 1%, 0.063 W, 0402"
Rsnub1: "RES, 8.2, 5%, 0.063 W, 0402"
TP1 TP2: "Test Point, Miniature, Red, TH"
TP3 TP5: "Test Point, Miniature, Black, TH"
U1: "LMS3635AQRNLRQ1, RNL0022A (VQFN-HR-22)"
U2: "Low Iq Always ON Smart Diode Controller, DDC0006A (SOT-6)"
U3: "Automotive USB Charging Port Controller and Power Switch with Short to BAT protection, RVC0020A"
U4: "USB 2.0 HIGH SPEED SIGNAL CONDITIONER, RGY0014A (VQFN-14)"
U5: "USB Type-C DFP Port Controller, DRF0008A"
U6: "Single Inverter Gate, DCK0005A (SOT-5)"
U7: "Zero Iq Reverse Polarity Protection Smart Diode Controller, DGK0008A (VSSOP-8)"
ZZ1: library part AssemblyNoteLabel
ZZ2 ZZ3 ZZ4: library part AssemblyNote

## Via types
v1: diameter 20, hole 8, Top Layer to Bottom Layer, tented both sides, 274 vias
v2: diameter 19.68, hole 7.87, Top Layer to Bottom Layer, 12 vias
v3: diameter 16, hole 8, Top Layer to Bottom Layer, tented both sides, 7 vias

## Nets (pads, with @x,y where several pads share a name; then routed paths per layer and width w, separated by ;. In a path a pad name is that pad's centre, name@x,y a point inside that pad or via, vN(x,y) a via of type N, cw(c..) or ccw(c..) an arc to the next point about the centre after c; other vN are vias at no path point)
AGND: C8.2 Cbias1.1 NTG1.1 RG1.1 U1.20 | length 217
  Top Layer w15: v1(1136.35,530) 1139.24,527.11 RG1.1@1158.75,527.11
  Bottom Layer w15: U1.20@1069.18,520 NTG1.1@1148.97,520 ; C8.2@1149.5,414.28 1149.5,456.85 Cbias1.1@1145.35,461 1145.35,516.37 NTG1.1@1148.97,520 ; NTG1.1@1152.35,523 1149.35,520 NTG1.1@1148.97,520
CATHODE: C5.1 L2.1 Q1.5 U2.4 U7.8
  other v1: 581.35,850 661.35,850 581.35,885 661.35,885 581.35,935 661.35,935 581.35,965 661.35,965
CC1: J2.A5 U5.8 | length 421.9
  Top Layer w8: v1@37.35,573 37.78,573.43 U5.8@56.82,573.43 ; v1@55.35,371 66.35,360 126.35,360 137.35,371 162.35,371 179.47,353.87 179.47,340.94 183.98,336.44 J2.A5@183.98,310.6 J2.A5@182.17,312.41
  Bottom Layer w8: v1(37.85,572.5) 32.47,567.13 32.47,392.87 v1(55.35,370)
CC2: J2.B5 U5.1 | length 570.9
  Top Layer w8: U5.1@56.82,502.57 37.91,502.57 27.35,492 27.35,365 19.74,357.39 19.74,232.61 46.35,206 240.35,206 252.87,218.53 J2.B5@252.87,243.67
CSPORT: C7.2 C10.1 RFA1.1 RFB1.1 U3.6 | length 1778.9
  Top Layer w10: C10.1@1060.42,561 1060.74,560.68 RFB1.1@1104.81,560.68 1106.35,562.22 RFA1.1@1106.35,589 1147.72,589 C7.2@1153.35,583.38 ; v1@1136.92,555 v1(1139.1,555)
  Signal Layer 2 w10: v1(130.77,970) 441.35,970 621.35,1150 801.35,1150 851.35,1100 999.47,1100 1113.47,986 1113.47,728.47 1052.5,667.5 1052.5,582 1081.5,553 1137.1,553 v1(1139.1,555)
D1+: U3.5 U4.10 | length 297.1
  Top Layer w9: U3.5@156.82,955.12 v1@156.82,1001.05
  Bottom Layer w9: v1(157.77,1009) 165.5,1016.73 165.5,1105.5 254.72,1194.72 U4.10@254.72,1220.04
D1-: U3.4 U4.9 | length 311.1
  Top Layer w9: U3.4@176.5,955.12 176.5,996.73 v1(188.77,1009)
  Bottom Layer w9: v1(188.77,1009) 182,1015.77 182,1100.65 274.4,1193.06 U4.9@274.4,1220.04
D2+: D4.2 J1.3 J1.@192.72,1880.47 U4.5 | length 560.3
  Bottom Layer w9: J1.3@192.72,1847.5 148,1802.78 148,1749 251.66,1645.34 D4.2@251.66,1408.09 254.72,1405.04 U4.5@254.72,1349.96
D2-: D4.1 J1.1 J1.@271.46,1735.78 U4.6 | length 559.9
  Bottom Layer w9: U4.6@274.4,1349.96 274.4,1391.46 D4.1@291.03,1408.09 291.03,1432.06 303.72,1444.75 327,1444.75 336,1453.75 336,1498.75 323.75,1511 275.75,1511 268.25,1518.5 268.25,1652 223,1697.25 223,1720.3 J1.1@271.46,1768.76 J1.1@276.35,1763.87
D+: J2.A6 J2.B6 U3.13 | length 758.4
  Top Layer w9: U3.13@178,843.39 178,668.35 211.47,634.87 211.47,405.56 211.35,405.43 211.35,361 201.35,351 v1(201.35,350) 203.66,347.68 J2.A6@203.66,310.6 ; J2.B6@233.19,243.67 234.59,245.07 234.59,270.25 v1(239.35,275)
  Top Layer w10: J2.A6@202.76,311.5 J2.A6@203.66,310.6
  Bottom Layer w9: v1(201.35,350) 223.72,372.37 250.61,372.37 263.72,359.27 263.72,321.51 239.35,297.14 v1(239.35,275)
D-: J2.A7 J2.B7 U3.14 | length 678
  Top Layer w9: U3.14@195,843.69 195,676.35 228.35,643 228.35,363 v1(241.35,350)
  Top Layer w10: v1@204.35,275 213.5,265.84 J2.B7@213.5,243.67 ; v1(241.35,350) 243.03,348.32 J2.A7@243.03,310.6
  Bottom Layer w9: v1(205.35,275) 205.35,287 241.35,323 v1(241.35,350)
EN_CHARGER: U3.7 U6.4 | length 255.7
  Top Layer w8: v1(60.15,1138) 60.15,1086.2 108.9,1037.45 108.9,947.87 v1(109.77,947) 109.77,931.3 U3.7@111.54,929.53
  Bottom Layer w8: U6.4@59.56,1112.29 59.56,1137.41 v1(60.15,1138)
GATEDRIVE: Q1.4 U2.5 U7.2 U7.6 | length 323.3
  Top Layer w15: U7.6@644.75,1038.48 677.22,1038.48 681.58,1034.12 706.91,1034.12 731.14,1009.89 ; U2.5@731.35,963.55 736.35,958.55 736.35,896 Q1.4@749.78,896 ; U2.5@733.35,963.55 733.35,1007.69 731.14,1009.89 ; U7.2@825.94,1009.89 731.14,1009.89
GND: C5.2 C9.1 C13.2 C14.2 C15.2 C16.2 C17.2 C18.2 C19.2 C20.2 C21.2 C22.2 C23.2 Cin1.2 Cin2.2 Cin3.2 Cin4.2 Cin5.2 COUT1.1 COUT2.1 COUT3.2 COUT4.2 D1.2 D2.1 D3.1 D4.3 J1.6 J1.@84.45,1656.55 J1.@84.45,1959.7 J1.@379.72,1656.55 J1.@379.72,1959.7 J1.@515.55,1879.48 J1.S1 J1.S2 J1.S3 J2.A1 J2.A12 J2.B1 J2.B12 NTG1.2 R10.1 R11.1 R12.1 R17.1 R19.1 R20.2 Rsnub1.1 TP3.1 TP5.1 U1.5 U1.6 U1.7 U1.8 U1.10 U1.11 U1.12 U1.13 U1.17 U2.2 U3.11 U3.21@186.35,900 U4.7 U4.15@235.03,1285 U5.6 U5.9 U6.3 | length 2011.6
  Top Layer w8: C23.2@57.91,679 C23.2@59.35,677.56 ; v2(86.35,538) 86.35,551 96.19,560.84 U5.6@96.19,573.43
  Top Layer w10: C15.2@212.59,1102.82 244.17,1102.82 v1(251.35,1110) ; R10.1@328.03,1062.82 328.03,1110.26 C19.2@328.77,1111
  Top Layer w12: v1(36.35,680) 58.91,680 C23.2@57.91,679 ; J2.A1@105.24,310.6 106.35,309.49 v1(106.35,272) ; J2.A12@341.46,310.6 341.46,279.89 v1(342.35,279) ; U2.2@733.35,1071.82 v1(733.35,1101.35)
  Top Layer w15: J2.B12@103.27,243.67 106.35,246.75 v1(106.35,272) ; C19.2@328.77,1111 352.77,1111 v1(354.77,1113) ; v1(342.35,279) 342.35,244.75 J2.B1@343.43,243.67 ; R12.1@361.35,945 R11.1@361.35,985 v1(361.35,1010)
  Top Layer w28: v1(1077.03,1198.68) 1199.15,1198.68 1199.15,223.68 1148.39,172.91
  Top Layer w50: COUT2.1@1008.73,172.91 1148.39,172.91
  Bottom Layer w10: D4.3@271.35,1459.28 271.35,1481.35 v1(273,1483) ; U1.17@1056.39,594.8 1073,611.42 v1(1073,622)
  Bottom Layer w12: v1(116.03,1174) 117.03,1175 C22.2@117.03,1201.44 ; v1(120.03,1376) 121.03,1375 R17.1@121.03,1354 ; v1(140.03,1409) 141.03,1410 R19.1@162.03,1410 ; v2(235.03,1285) 264.56,1314.53 U4.7@299.99,1314.53 349.06,1314.53 C21.2@352.03,1311.56 352.03,1338 v1(351.03,1339)
  other v1: 781.35,100 813.65,100 845,100 875,100 905,100 935,100 965,100 995,100 1025,100 1055,100 1088.65,100 781.35,130 815,130 846.35,130 876.35,130 906.35,130 936.35,130 966.35,130 996.35,130 1026.35,130 1056.35,130 1090,130 1121.35,130 720,160 750,160 781.35,160 1121.35,160 781.35,190 1121.35,190 700,195 781.35,220 446.35,225 481.35,225 511.35,225 541.35,225 571.35,225 600,225 630,225 665,225 700,225 1146.35,234.13 446.35,255 1147.35,260.13 1199.15,260 446.35,285 1147.35,287.13 1199.15,290 1199.15,320 446.35,325 1079,349 1199.15,350 446.35,360 446.35,390 1199.15,390 446.35,420 1199.15,420 776.68,432.78 710,435 745.39,435 810,435 845,435 446.35,450 1199.15,450 710,460 1199.15,480 631.35,485 660,485 710,485 446.35,490 496.35,490 141.35,515 631.35,515 660,515 710,515 1199.15,515 496.35,520 446.35,525 631.35,545 660,545 1199.15,545 496.35,550 446.35,555 141.35,560 631.35,575 660,575 690.94,575 1199.15,575 496.35,580 446.35,585 1199.15,605 630,610 660,610 690,610 720,610 756,610 785,610 815,610 850,610 495,615 445,620 510,645 540,645 570,645 600,645 631.35,645 661.35,645 691.35,645 721.35,645 756.35,645 786.35,645 815,645 846.35,645 401.17,670 508.65,680 538.65,680 568.65,680 598.65,680 630,680 660,680 690,680 720,680 755,680 785,680 815,680 846.35,680 401.35,705 815,710 846.35,710 1137.69,724 105.59,735 815,740 846.35,740 1138.69,758 406.35,760 815,770 846.35,770 106.35,790 406.35,790 813.65,800 845,800 1136.35,800 1137.35,834 1137.35,869 1138.35,903 1136.35,945 1137.35,979 1137.35,1014 46.35,1025 384.55,1041 1138.35,1048 446.35,1060 481.35,1060 386.35,1070 1136.35,1095 1137.35,1129 986.03,1129.68 1076.03,1129.68 987.03,1163.68 1077.03,1163.68 1137.35,1164 1138.35,1198 987.03,1198.68 988.03,1232.68 1078.03,1232.68 1136.35,1235 596.35,1250 626.35,1250 661.35,1250 596.35,1410 626.35,1410 656.35,1410
  other v2: 145.01,878.35 186.35,878.35 227.69,878.35 145.01,921.65 186.35,921.65 227.69,921.65 235.03,1254.49 204.52,1285 265.54,1285 235.03,1315.51
"INPUT POWER": C6.1 C11.1 C13.1 D1.1 J1.5 J1.@515.55,1736.77 Q1.1 Q1.2 Q1.3 TP2.1 U2.3 U2.6 U7.4 | length 736.6
  Top Layer w20: U2.3@695.95,1071.82 695.95,1119.6 711.35,1135 806.35,1135 819.94,1121.4 U7.4@819.94,1065.21 ; v1@900.42,1064.07 921.35,1043.14 v1(921.35,1020)
  Top Layer w30: Q1.1@749.78,753.06 Q1.3@749.78,846 783.35,846 807.35,870 807.35,925.76 ; U2.6@770.75,963.55 770.75,962.36 807.35,925.76 ; 807.35,929 807.35,925.76 ; v1(921.35,1020) 921.35,988.51 862.84,930 811.59,930 807.35,925.76
  other v1: 877.28,1069.07 906.35,1070 876,1150 905.29,1150 766.35,1250 796.35,1250 831.35,1250 771.35,1411.82 801.35,1411.82 831.35,1411.82
NetC1_1: C1.1 U7.7 | length 84.1
  Top Layer w15: C1.1@567.35,1029 583.46,1012.89 U7.7@644.75,1012.89
NetC1_2: C1.2 U7.1 | length 447.3
  Top Layer w15: C1.2@554.35,1126 620.35,1126 v1(646.35,1100) v1@647.35,1101 ; U7.1@819.94,987.3 859.05,987.3 863.65,987.3 v1(881.35,1005)
  Signal Layer 2 w15: v1(646.35,1100) 741.35,1005 v1(881.35,1005)
NetC6_2: C6.2 C9.2 | length 62
  Top Layer w40: C6.2@953,1577.5 C9.2@953,1639.5
NetC8_1: C8.1 U1.1 | length 161.1
  Bottom Layer w10: U1.1@1056.39,445.2 1056.39,441.68 1081.06,417 1081.06,416.94 1105.68,392.32 1105.68,347.32 1113.81,339.19 C8.1@1145.16,339.19
NetC10_2: C10.2 RFB1.2 RG1.2 U1.21 | length 165.9
  Top Layer w10: C10.2@1060.42,521 1104.5,521 RFB1.2@1104.81,520.68 1104.81,496.54 v1(1106.35,495) 1133.61,495 1141.5,487.11 RG1.2@1158.75,487.11
  Bottom Layer w10: U1.21@1069.18,500.32 1101.03,500.32 v1(1106.35,495)
NetC11_2: C11.2 U2.1 | length 72.4
  Top Layer w20: U2.1@770.75,1071.82 770.75,1100.75 v1(771.35,1101.35)
  Bottom Layer w20: v1(771.35,1101.35) 776.48,1106.48 C11.2@811.82,1106.48
NetC19_1: C19.1 R10.2 U3.1 | length 169.9
  Top Layer w9: U3.1@235.56,955.12 235.56,981.79 288.03,1034.26 R10.2@288.03,1062.82 ; R10.2@288.03,1070.82 288.03,1110.26 C19.1@288.77,1111
NetC20_1: C20.1 D2.2 R4.1 U3.12 | length 192
  Top Layer w10: v1@148.77,817 156.82,825.05 U3.12@156.82,844.88
  Bottom Layer w10: v1(140.77,814) v1@141.38,814.61
  Bottom Layer w15: v1@141.38,814.61 R4.1@166.95,814.61 166.95,776.11 159.14,768.3 159.14,719.34 D2.2@184.48,694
